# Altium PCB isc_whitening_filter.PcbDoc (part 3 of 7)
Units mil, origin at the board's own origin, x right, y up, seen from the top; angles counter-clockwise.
Board outline 8440 x 7000 mil, 6 copper layers (Top Layer, MidLayer1, InternalPlane1, Internal Plane 3, InternalPlane2, Bottom Layer); 550 components, 434 nets, 2189 pads, 806 vias.
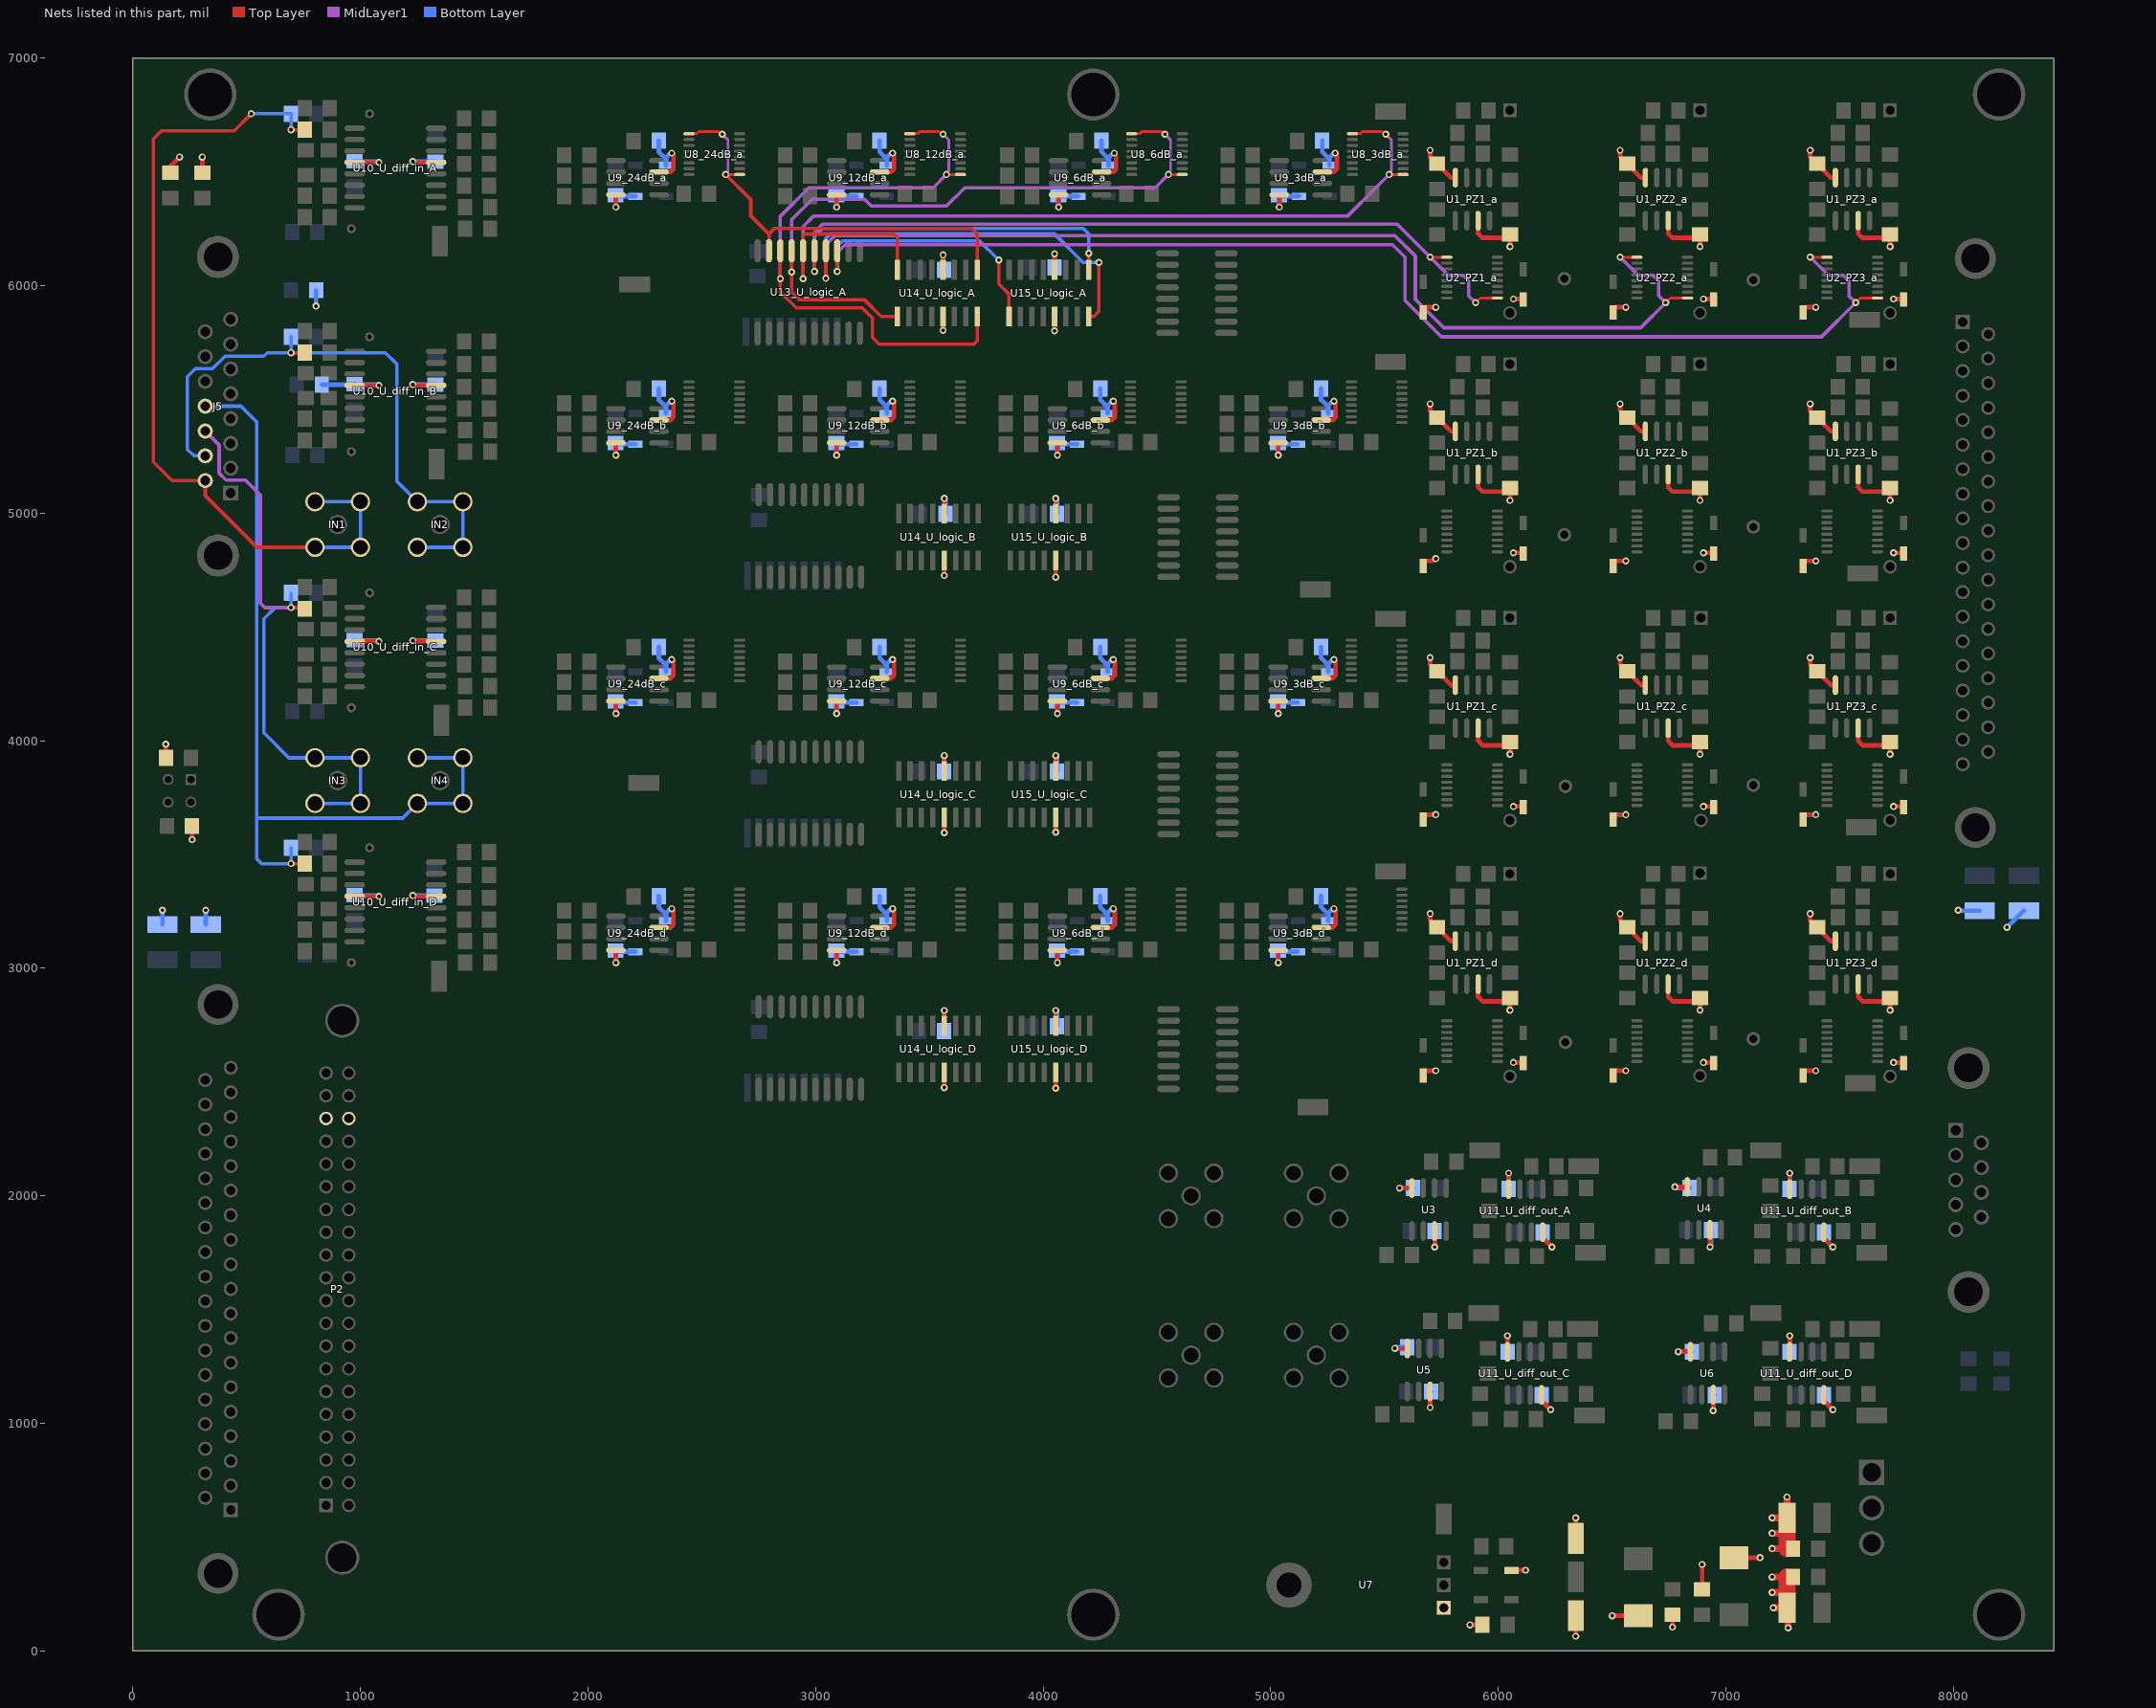
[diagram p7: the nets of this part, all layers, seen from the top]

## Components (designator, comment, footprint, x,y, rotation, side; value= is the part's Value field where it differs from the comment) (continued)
U8_6dB_b "ADG1436YRUZ-REEL7" ADI-RU-16_L 4495,5487.8 r180 top (schematic designator U8)
U8_6dB_c "ADG1436YRUZ-REEL7" ADI-RU-16_L 4495,4352.8 r180 top (schematic designator U8)
U8_6dB_d "ADG1436YRUZ-REEL7" ADI-RU-16_L 4495,3257.8 r180 top (schematic designator U8)
U8_12dB_a "ADG1436YRUZ-REEL7" ADI-RU-16_L 3525,6577.8 r180 top (schematic designator U8)
U8_12dB_b "ADG1436YRUZ-REEL7" ADI-RU-16_L 3525,5487.8 r180 top (schematic designator U8)
U8_12dB_c "ADG1436YRUZ-REEL7" ADI-RU-16_L 3525,4352.8 r180 top (schematic designator U8)
U8_12dB_d "ADG1436YRUZ-REEL7" ADI-RU-16_L 3525,3257.8 r180 top (schematic designator U8)
U8_24dB_a "ADG1436YRUZ-REEL7" ADI-RU-16_L 2555,6577.8 r180 top (schematic designator U8)
U8_24dB_b "ADG1436YRUZ-REEL7" ADI-RU-16_L 2555,5487.8 r180 top (schematic designator U8)
U8_24dB_c "ADG1436YRUZ-REEL7" ADI-RU-16_L 2555,4352.8 r180 top (schematic designator U8)
U8_24dB_d "ADG1436YRUZ-REEL7" ADI-RU-16_L 2555,3257.8 r180 top (schematic designator U8)
U9_3dB_a "OP27GS" SOIC127P600-8N 5132,6474 r0 top (schematic designator U9)
U9_3dB_b "OP27GS" SOIC127P600-8N 5127,5384 r0 top (schematic designator U9)
U9_3dB_c "OP27GS" SOIC127P600-8N 5127,4249 r0 top (schematic designator U9)
U9_3dB_d "OP27GS" SOIC127P600-8N 5127,3154 r0 top (schematic designator U9)
U9_6dB_a "OP27GS" SOIC127P600-8N 4162,6474 r0 top (schematic designator U9)
U9_6dB_b "OP27GS" SOIC127P600-8N 4157,5384 r0 top (schematic designator U9)
U9_6dB_c "OP27GS" SOIC127P600-8N 4157,4249 r0 top (schematic designator U9)
U9_6dB_d "OP27GS" SOIC127P600-8N 4157,3154 r0 top (schematic designator U9)
U9_12dB_a "OP27GS" SOIC127P600-8N 3187,6474 r0 top (schematic designator U9)
U9_12dB_b "OP27GS" SOIC127P600-8N 3187,5384 r0 top (schematic designator U9)
U9_12dB_c "OP27GS" SOIC127P600-8N 3187,4249 r0 top (schematic designator U9)
U9_12dB_d "OP27GS" SOIC127P600-8N 3187,3154 r0 top (schematic designator U9)
U9_24dB_a "OP27GS" SOIC127P600-8N 2217,6474 r0 top (schematic designator U9)
U9_24dB_b "OP27GS" SOIC127P600-8N 2217,5384 r0 top (schematic designator U9)
U9_24dB_c "OP27GS" SOIC127P600-8N 2217,4249 r0 top (schematic designator U9)
U9_24dB_d "OP27GS" SOIC127P600-8N 2217,3154 r0 top (schematic designator U9)
U10_U_diff_in_A "LT1125CSW" SOIC127P1030-16N 1153.66,6516.5 r0 top (schematic designator U10)
U10_U_diff_in_B "LT1125CSW" SOIC127P1030-16N 1153.66,5536.5 r0 top (schematic designator U10)
U10_U_diff_in_C "LT1125CSW" SOIC127P1030-16N 1153.66,4411.5 r0 top (schematic designator U10)
U10_U_diff_in_D "LT1125CSW" SOIC127P1030-16N 1153.66,3291.5 r0 top (schematic designator U10)
U11_U_diff_out_A "AD8672ARZ" SOIC127P600-8N 6120,1935 r270 top (schematic designator U11)
U11_U_diff_out_B "AD8672ARZ" SOIC127P600-8N 7355,1935 r270 top (schematic designator U11)
U11_U_diff_out_C "AD8672ARZ" SOIC127P600-8N 6115,1220 r270 top (schematic designator U11)
U11_U_diff_out_D "AD8672ARZ" SOIC127P600-8N 7355,1220 r270 top (schematic designator U11)
U13_U_logic_A "74ALS573" DW020_M 2970,5972 r90 top (schematic designator U13)
U13_U_logic_B "74ALS573" DW020_M 2975,4900 r90 top (schematic designator U13)
U13_U_logic_C "74ALS573" DW020_M 2975,3770 r90 top (schematic designator U13)
U13_U_logic_D "74ALS573" DW020_M 2975,2650 r90 top (schematic designator U13)
U14_U_logic_A "DG412" SOIC16 3535,5967 r180 top (schematic designator U14)
U14_U_logic_B "DG412" SOIC16 3540,4895 r180 top (schematic designator U14)
U14_U_logic_C "DG412" SOIC16 3540,3765 r180 top (schematic designator U14)
U14_U_logic_D "DG412" SOIC16 3540,2645 r180 top (schematic designator U14)
U15_U_logic_A "DG412" SOIC16 4025,5967 r180 top (schematic designator U15)
U15_U_logic_B "DG412" SOIC16 4030,4895 r180 top (schematic designator U15)
U15_U_logic_C "DG412" SOIC16 4030,3765 r180 top (schematic designator U15)
U15_U_logic_D "DG412" SOIC16 4030,2645 r180 top (schematic designator U15)

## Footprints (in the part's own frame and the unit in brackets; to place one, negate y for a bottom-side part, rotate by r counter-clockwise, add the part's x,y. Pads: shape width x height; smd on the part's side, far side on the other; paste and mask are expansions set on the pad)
1812 [mm]
  rect 1.9x3.4 smd: 1(-1.95,0) 2(1.95,0)
  silkscreen extent -0.7,-1.6 0.7,1.6, body extent -2.48,-1.9 2.47,1.91, height 3.42
3216[1206] [mm]
  rect 1.6x1.8 smd: 1(-1.4,0) 2(1.4,0)
  silkscreen extent -0.16,-0.8 0.15,0.79, body extent -1.67,-0.86 1.68,0.87, height 0.85
7343-31 [mil]
  rect 100x125 smd: 1(0,0) 2(-250,0)
  silkscreen extent -290,-85 40,85, body extent -271,-88 21,88
ADI-RU-16_L [mm] "SOP, 16-Leads, Body 5x4.4mm, Pitch 0.65mm, IPC High Density"
  oval 1.25x0.35 smd: 1(-2.825,2.275) 2(-2.825,1.625) 3(-2.825,0.975) 4(-2.825,0.325) 5(-2.825,-0.325) 6(-2.825,-0.975) 7(-2.825,-1.625) 8(-2.825,-2.275) 9(2.825,-2.275) 10(2.825,-1.625) 11(2.825,-0.975) 12(2.825,-0.325) 13(2.825,0.325) 14(2.825,0.975) 15(2.825,1.625) 16(2.825,2.275)
  silkscreen extent -2.95,-2.55 1.8,3.12, body extent -2.25,-2.55 2.25,2.55, height 1.2
DB37/F/RA/125MT [mil]
  rect 62x62 hole 40.5: 1(0,0)
  round 62 hole 40.5: 2(107,0) 3(215,0) 4(324,0) 5(431,0) 6(539,0) 7(647,0) 8(755,0) 9(863,0) 10(971,0) 11(1079,0) 12(1187,0) 13(1295,0) 14(1403,0) 15(1511,0) 16(1619,0) 17(1727,0) 18(1835,0) 19(1943,0) 20(53,112) 21(161,112) 22(269,112) 23(377,112) 24(485,112) 25(593,112) 26(701,112) 27(809,112) 28(917,112) 29(1025,112) 30(1133,112) 31(1241,112) 32(1349,112) 33(1457,112) 34(1565,112) 35(1673,112) 36(1781,112) 37(1889,112)
  round 180 hole 125.9: 38(-279,56) 39(2221,56)
  silkscreen extent -394,-98 2336,666, body extent -402,-72 2336,673, height 497
DSUB1.385-2H9 [mm]
  rect 1.69x1.69 hole 1.097: 1(-5.54,-10.92)
  round 1.69 hole 1.097: 2(-2.77,-10.92) 3(0,-10.92) 4(2.77,-10.92) 5(5.54,-10.92) 6(-4.155,-8.08) 7(-1.385,-8.08) 8(1.385,-8.08) 9(4.155,-8.08)
  round 4.699 hole 3.198: 10(-12.495,-9.5) 11(12.495,-9.5)
  silkscreen extent -15.4,-12.4 15.4,6, body extent -15.49,-12.67 15.49,6.22, height 12.62
DSUB1.385-2H15 [mm]
  rect 1.69x1.69 hole 1.097: 1(-9.695,-10.92)
  round 1.69 hole 1.097: 2(-6.925,-10.92) 3(-4.155,-10.92) 4(-1.385,-10.92) 5(1.385,-10.92) 6(4.155,-10.92) 7(6.925,-10.92) 8(9.695,-10.92) 9(-8.31,-8.08) 10(-5.54,-8.08) 11(-2.77,-8.08) 12(0,-8.08) 13(2.77,-8.08) 14(5.54,-8.08) 15(8.31,-8.08)
  round 4.699 hole 3.198: 16(-16.66,-9.5) 17(16.66,-9.5)
  silkscreen extent -20,-12.5 20,6, body extent -19.68,-12.67 19.69,6.22, height 12.62
DW020_M [mm]
  oval 2.6x0.7 smd: 1(-4.6,5.715) 2(-4.6,4.445) 3(-4.6,3.175) 4(-4.6,1.905) 5(-4.6,0.635) 6(-4.6,-0.635) 7(-4.6,-1.905) 8(-4.6,-3.175) 9(-4.6,-4.445) 10(-4.6,-5.715) 11(4.6,-5.715) 12(4.6,-4.445) 13(4.6,-3.175) 14(4.6,-1.905) 15(4.6,-0.635) 16(4.6,0.635) 17(4.6,1.905) 18(4.6,3.175) 19(4.6,4.445) 20(4.6,5.715)
  silkscreen extent -4.72,-6.5 2.9,6.74, body extent -5.24,-6.42 5.24,6.43, height 2.65
ECQ-E1106KF_Side [mil]
  rect 60x60 hole 40.5: 1(0,0)
  round 60 hole 40.5: 2(890,0)
  silkscreen extent -50,-50 950,340, body extent -62,-688 962,926
Molex_156_RA_3 [mil]
  rect 110x110 hole 80: 1(0,0)
  round 110 hole 80: 2(0,-156) 3(0,-312)
  silkscreen extent 213,-382 792,70, body extent -24,-386 792,76, height 394
"my LUMEX Dual LED" [mil]
  rect 48x48 hole 32: 1(0,0)
  round 48 hole 32: 2(0,-100) 3(-100,0) 4(-100,-100)
  silkscreen extent -320,-140 45,40, body extent -379,-135 45,35, height 380
MY_40-pin_Header_RA [mil]
  rect 60x60 hole 40.5 mask+0: 1(230,-71)
  round 60 hole 40.5 mask+0: 2(230,29) 3(330,-71) 4(330,29) 5(430,-71) 6(430,29) 7(530,-71) 8(530,29) 9(630,-71) 10(630,29) 11(730,-71) 12(730,29) 13(830,-71) 14(830,29) 15(930,-71) 16(930,29) 17(1030,-71) 18(1030,29) 19(1130,-71) 20(1130,29) 21(1230,-71) 22(1230,29) 23(1330,-71) 24(1330,29) 25(1430,-71) 26(1430,29) 27(1530,-71) 28(1530,29) 29(1630,-71) 30(1630,29) 31(1730,-71) 32(1730,29) 33(1830,-71) 34(1830,29) 35(1930,-71) 36(1930,29) 37(2030,-71) 38(2030,29) 39(2130,-71) 40(2130,29)
  round 150 hole 125.9 mask+0: 41(2360,0) 42(0,0)
  silkscreen extent -220,-120 2580,440, body extent -200,-148 2560,978, height 344
MY_TO220 [mil]
  rect 62x62 hole 40.5: 1(-100,0) 2(0,0) 3(100,0)
  round 200 hole 110: 4(0,680)
  silkscreen extent -200,60 200,800, body extent -200,-85 200,795, height 180
SMA [mil] "SMA straight PCB"
  round 85 hole 65: 1(0,0) 2(-100,100) 2(-100,-100) 2(100,100) 2(100,-100)
  silkscreen extent -160,-160 160,160, body extent -126,-126 126,126, height 370
sod123 [mm]
  rect 1.6x0.8 smd: 1(-1.7,0) 2(1.7,0)
  silkscreen extent -1.45,-0.85 1.45,0.85, body extent -1.95,-0.9 1.95,0.9, height 1.18
SOIC16 [mm]
  rect 0.6x2.2 smd: 1(-4.445,-2.6) 2(-3.175,-2.6) 3(-1.905,-2.6) 4(-0.635,-2.6) 5(0.635,-2.6) 6(1.905,-2.6) 7(3.175,-2.6) 8(4.445,-2.6) 9(4.445,2.6) 10(3.175,2.6) 11(1.905,2.6) 12(0.635,2.6) 13(-0.635,2.6) 14(-1.905,2.6) 15(-3.175,2.6) 16(-4.445,2.6)
  silkscreen extent -5.42,-2.72 5,1.1, body extent -4.98,-3.06 4.97,3.06, height 1.75
SOIC127P600-8N [mm]
  oval 2.2x0.6 smd: 1(-2.4,1.905) 2(-2.4,0.635) 3(-2.4,-0.635) 4(-2.4,-1.905) 5(2.4,-1.905) 6(2.4,-0.635) 7(2.4,0.635) 8(2.4,1.905)
  silkscreen extent -2.52,-2.5 0.9,2.88, body extent -3.06,-2.47 3.06,2.48, height 1.75
SOIC127P1030-16N [mm]
  oval 2.3x0.6 smd: 1(-4.55,4.445) 2(-4.55,3.175) 3(-4.55,1.905) 4(-4.55,0.635) 5(-4.55,-0.635) 6(-4.55,-1.905) 7(-4.55,-3.175) 8(-4.55,-4.445) 9(4.55,-4.445) 10(4.55,-3.175) 11(4.55,-1.905) 12(4.55,-0.635) 13(4.55,0.635) 14(4.55,1.905) 15(4.55,3.175) 16(4.55,4.445)
  silkscreen extent -4.67,-5.25 3,5.42, body extent -5.24,-5.18 5.24,5.18, height 2.65
SOP127P760X300-16M [mm]
  oval 2.55x0.7 smd: 1(-3.275,4.445) 2(-3.275,3.175) 3(-3.275,1.905) 4(-3.275,0.635) 5(-3.275,-0.635) 6(-3.275,-1.905) 7(-3.275,-3.175) 8(-3.275,-4.445) 9(3.275,-4.445) 10(3.275,-3.175) 11(3.275,-1.905) 12(3.275,-0.635) 13(3.275,0.635) 14(3.275,1.905) 15(3.275,3.175) 16(3.275,4.445)
  silkscreen extent -3.4,-5.65 1.6,5.65, body extent -3.06,-4.97 3.06,4.98, height 1.75
SRT9 [mil]
  rect 125x30 smd: 1(0,0) 2(0,-50) 3(0,-100) 4(0,-150) 5(0,-200) 6(0,-250) 7(0,-300) 8(0,-350) 9(0,-400)
  silkscreen extent -53,-450 55,52, body extent -40,-450 40,50, height 100
TP_SMT_MICRO [mil]
  rect 135x70 smd: 1(0,0)
  body extent -53,-20 52,20, height 60

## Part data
C1_PZ1_a C1_PZ1_b C1_PZ1_c C1_PZ1_d C1_PZ2_a C1_PZ2_b C1_PZ2_c C1_PZ2_d C1_PZ3_a C1_PZ3_b C1_PZ3_c C1_PZ3_d C3_PZ1_a C3_PZ1_b C3_PZ1_c C3_PZ1_d C3_PZ2_a C3_PZ2_b C3_PZ2_c C3_PZ2_d C3_PZ3_a C3_PZ3_b C3_PZ3_c C3_PZ3_d C6 C8 C9 C11 C12 C14 C15 C17 C19 C22 C24_3dB_a C24_3dB_b C24_3dB_c C24_3dB_d C24_6dB_a C24_6dB_b C24_6dB_c C24_6dB_d C24_12dB_a C24_12dB_b C24_12dB_c C24_12dB_d C24_24dB_a C24_24dB_b C24_24dB_c C24_24dB_d C26_3dB_a C26_3dB_b C26_3dB_c C26_3dB_d C26_6dB_a C26_6dB_b C26_6dB_c C26_6dB_d C26_12dB_a C26_12dB_b C26_12dB_c C26_12dB_d C26_24dB_a C26_24dB_b C26_24dB_c C26_24dB_d C30_U_diff_out_A C30_U_diff_out_B C30_U_diff_out_C C30_U_diff_out_D C31_U_diff_out_A C31_U_diff_out_B C31_U_diff_out_C C31_U_diff_out_D C32_U_logic_A C32_U_logic_B C32_U_logic_C C32_U_logic_D C33_U_logic_A C33_U_logic_B C33_U_logic_C C33_U_logic_D C36_U_logic_A C36_U_logic_B C36_U_logic_C C36_U_logic_D: library part Cap, "Capacitor", Supplier Part Number 1=399-C1206C104K5RACTUCT-ND
C2_PZ1_a C2_PZ1_b C2_PZ1_c C2_PZ1_d C2_PZ2_a C2_PZ2_b C2_PZ2_c C2_PZ2_d C2_PZ3_a C2_PZ3_b C2_PZ3_c C2_PZ3_d C7 C10 C13 C16 C25_3dB_a C25_3dB_b C25_3dB_c C25_3dB_d C25_6dB_a C25_6dB_b C25_6dB_c C25_6dB_d C25_12dB_a C25_12dB_b C25_12dB_c C25_12dB_d C25_24dB_a C25_24dB_b C25_24dB_c C25_24dB_d: library part Cap, "Capacitor", Supplier Part Number 1=399-C1206C680K1HACAUTOCT-ND
C4_PZ1_a C4_PZ1_b C4_PZ1_c C4_PZ1_d C4_PZ2_a C4_PZ2_b C4_PZ2_c C4_PZ2_d C4_PZ3_a C4_PZ3_b C4_PZ3_c C4_PZ3_d: library part Cap, "Capacitor", Supplier Part Number 1=399-C1206C101K5HACTUCT-ND
C5_PZ1_a C5_PZ1_b C5_PZ1_c C5_PZ1_d C5_PZ2_a C5_PZ2_b C5_PZ2_c C5_PZ2_d C5_PZ3_a C5_PZ3_b C5_PZ3_c C5_PZ3_d: library part MYCAP, "Capacitor", Supplier Part Number 1=P14629-ND
C18 C23: library part "CAPACITOR POL", "Polarized Cap", Supplier Part Number 1=478-1722-1-ND
C20 C21 C28_U_diff_in_A C28_U_diff_in_B C28_U_diff_in_C C28_U_diff_in_D C29_U_diff_in_A C29_U_diff_in_B C29_U_diff_in_C C29_U_diff_in_D C34 C35: library part MYCAP, "Capacitor", Supplier Part Number 1=1276-1068-1-ND
C27_3dB_a C27_3dB_b C27_3dB_c C27_3dB_d C27_6dB_a C27_6dB_b C27_6dB_c C27_6dB_d C27_12dB_a C27_12dB_b C27_12dB_c C27_12dB_d C27_24dB_a C27_24dB_b C27_24dB_c C27_24dB_d: library part Cap, "Capacitor"
C37_U_diff_in_A C37_U_diff_in_B C37_U_diff_in_C C37_U_diff_in_D C38_U_diff_in_A C38_U_diff_in_B C38_U_diff_in_C C38_U_diff_in_D C39_U_diff_in_A C39_U_diff_in_B C39_U_diff_in_C C39_U_diff_in_D: library part MYCAP, "Capacitor", Supplier Part Number 1=13-CC1206FRNPO9BN562CT-ND
D1_PZ1_a D1_PZ1_b D1_PZ1_c D1_PZ1_d D1_PZ2_a D1_PZ2_b D1_PZ2_c D1_PZ2_d D1_PZ3_a D1_PZ3_b D1_PZ3_c D1_PZ3_d D2_PZ1_a D2_PZ1_b D2_PZ1_c D2_PZ1_d D2_PZ2_a D2_PZ2_b D2_PZ2_c D2_PZ2_d D2_PZ3_a D2_PZ3_b D2_PZ3_c D2_PZ3_d D3 D5 D6_3dB_a D6_3dB_b D6_3dB_c D6_3dB_d D6_6dB_a D6_6dB_b D6_6dB_c D6_6dB_d D6_12dB_a D6_12dB_b D6_12dB_c D6_12dB_d D6_24dB_a D6_24dB_b D6_24dB_c D6_24dB_d D7_3dB_a D7_3dB_b D7_3dB_c D7_3dB_d D7_6dB_a D7_6dB_b D7_6dB_c D7_6dB_d D7_12dB_a D7_12dB_b D7_12dB_c D7_12dB_d D7_24dB_a D7_24dB_b D7_24dB_c D7_24dB_d: library part Diode, "Diode 1 Amp", Supplier Part Number 1=RB160MM-60CT-ND
D4: library part "Dual Stacked LED", "Dual Green LED", Supplier Part Number 1=67-1321-ND
IN1 IN2 IN3 IN4 OUT1 OUT2 OUT3 OUT4: "SMA, PCB Mount, Right Angle", Supplier Part Number 1=900-0732517040-ND
J5: "15 Position, Right Angle, Receptacle Assembly", Supplier Part Number 1=D15S33E6GX00LF-ND
J6: "9 Position, Right Angle,Receptacle Assembly", Supplier Part Number 1=609-6160-ND
L1 L2: library part INDUCTOR, "INDUCTOR"
L5 L6 L7 L8: library part INDUCTOR, "INDUCTOR", Supplier Part Number 1=CC453232-100KLCT-ND
P1 P3: "Standard D-Subminiature Connector 37 pin", Supplier Part Number 1=D37S33E6GX00LF-ND
P2: "Header, 20-Pin, Dual row, Right Angle", Supplier Part Number 1=609-86130402113345E1LF-ND
P4: "Header, 3-Pin, Right Angle", Supplier Part Number 1=WM5236-ND
R1_PZ1_a R1_PZ1_b R1_PZ1_c R1_PZ1_d R1_PZ2_a R1_PZ2_b R1_PZ2_c R1_PZ2_d R1_PZ3_a R1_PZ3_b R1_PZ3_c R1_PZ3_d R11_3dB_a R11_3dB_b R11_3dB_c R11_3dB_d R11_6dB_a R11_6dB_b R11_6dB_c R11_6dB_d R11_12dB_a R11_12dB_b R11_12dB_c R11_12dB_d R11_24dB_a R11_24dB_b R11_24dB_c R11_24dB_d R30_PZ1_a R30_PZ1_b R30_PZ1_c R30_PZ1_d R30_PZ2_a R30_PZ2_b R30_PZ2_c R30_PZ2_d R30_PZ3_a R30_PZ3_b R30_PZ3_c R30_PZ3_d: library part Res1, "Resistor", Supplier Part Number 1=10-ERA-8AEB153VCT-ND
R2_PZ1_a R2_PZ1_b R2_PZ1_c R2_PZ1_d R2_PZ2_a R2_PZ2_b R2_PZ2_c R2_PZ2_d R2_PZ3_a R2_PZ3_b R2_PZ3_c R2_PZ3_d: library part Res1, "Resistor", Supplier Part Number 1=P18589CT-ND
R3 R4 R5 R6 R17_U_diff_in_A R17_U_diff_in_B R17_U_diff_in_C R17_U_diff_in_D R19_U_diff_in_A R19_U_diff_in_B R19_U_diff_in_C R19_U_diff_in_D R23_U_diff_out_A R23_U_diff_out_B R23_U_diff_out_C R23_U_diff_out_D R26_U_diff_out_A R26_U_diff_out_B R26_U_diff_out_C R26_U_diff_out_D R35 R36 R38 R39: library part Res1, "Resistor", Supplier Part Number 1=HCJ1206ZT0R00CT-ND
R7 R8 R9 R10 R32_U_diff_in_A R32_U_diff_in_B R32_U_diff_in_C R32_U_diff_in_D R33_U_diff_in_A R33_U_diff_in_B R33_U_diff_in_C R33_U_diff_in_D: library part Res1, "Resistor", Supplier Part Number 1=P1.0KBCCT-ND
R12_3dB_a R12_3dB_b R12_3dB_c R12_3dB_d R12_6dB_a R12_6dB_b R12_6dB_c R12_6dB_d R12_12dB_a R12_12dB_b R12_12dB_c R12_12dB_d R12_24dB_a R12_24dB_b R12_24dB_c R12_24dB_d R13_3dB_a R13_3dB_b R13_3dB_c R13_3dB_d R13_6dB_a R13_6dB_b R13_6dB_c R13_6dB_d R13_12dB_a R13_12dB_b R13_12dB_c R13_12dB_d R13_24dB_a R13_24dB_b R13_24dB_c R13_24dB_d R18_U_diff_in_A R18_U_diff_in_B R18_U_diff_in_C R18_U_diff_in_D: library part Res1, "Resistor"
R14_U_diff_in_A R14_U_diff_in_B R14_U_diff_in_C R14_U_diff_in_D R22_U_diff_in_A R22_U_diff_in_B R22_U_diff_in_C R22_U_diff_in_D: library part Res1, "Resistor", Supplier Part Number 1=P1.0MBCCT-ND
R15_U_diff_in_A R15_U_diff_in_B R15_U_diff_in_C R15_U_diff_in_D R21_U_diff_in_A R21_U_diff_in_B R21_U_diff_in_C R21_U_diff_in_D: library part Res1, "Resistor", Supplier Part Number 1=10-ERA-8AEB302VCT-ND
R16_U_diff_in_A R16_U_diff_in_B R16_U_diff_in_C R16_U_diff_in_D R20_U_diff_in_A R20_U_diff_in_B R20_U_diff_in_C R20_U_diff_in_D: library part Res1, "Resistor", Supplier Part Number 1=P1.5KBCCT-ND
R24_U_diff_out_A R24_U_diff_out_B R24_U_diff_out_C R24_U_diff_out_D R25_U_diff_out_A R25_U_diff_out_B R25_U_diff_out_C R25_U_diff_out_D R27_U_diff_out_A R27_U_diff_out_B R27_U_diff_out_C R27_U_diff_out_D R28_U_diff_out_A R28_U_diff_out_B R28_U_diff_out_C R28_U_diff_out_D: library part Res1, "Resistor", Supplier Part Number 1=P4.99KBCCT-ND
R29_U_logic_A R29_U_logic_B R29_U_logic_C R29_U_logic_D: library part RES_BUS_8, "8 Bus Resistor", Supplier Part Number 1=60-752091103GPTR7CT-ND
R31_U_logic_A R31_U_logic_B R31_U_logic_C R31_U_logic_D: library part "Res Pack3", "Isolated Resistor Network", Supplier Part Number 1=4816P-1-561LFCT-ND
R34 R37: library part Res1, "Resistor", Supplier Part Number 1=P49.9BCCT-ND
TP1 TP2 TP3 TP4 TP5 TP6 TP7_U_diff_out_A TP7_U_diff_out_B TP7_U_diff_out_C TP7_U_diff_out_D TP8_U_diff_out_A TP8_U_diff_out_B TP8_U_diff_out_C TP8_U_diff_out_D TP9 TP9_U_diff_out_A TP9_U_diff_out_B TP9_U_diff_out_C TP9_U_diff_out_D TP10 TP11 TP12 TP13 TP14 TP15 TP16 TP17 TP18 TP19 TP20 TP21 TP22: library part TESTPT, "PCB Testpoint", Supplier Part Number 1=36-5016CT-ND
U1_PZ1_a U1_PZ1_b U1_PZ1_c U1_PZ1_d U1_PZ2_a U1_PZ2_b U1_PZ2_c U1_PZ2_d U1_PZ3_a U1_PZ3_b U1_PZ3_c U1_PZ3_d U3 U4 U5 U6 U9_3dB_a U9_3dB_b U9_3dB_c U9_3dB_d U9_6dB_a U9_6dB_b U9_6dB_c U9_6dB_d U9_12dB_a U9_12dB_b U9_12dB_c U9_12dB_d U9_24dB_a U9_24dB_b U9_24dB_c U9_24dB_d: library part OP184ES, "Video Operational Amplifier", Supplier Part Number 1=OP27GSZ-REEL7CT-ND
U2_PZ1_a U2_PZ1_b U2_PZ1_c U2_PZ1_d U2_PZ2_a U2_PZ2_b U2_PZ2_c U2_PZ2_d U2_PZ3_a U2_PZ3_b U2_PZ3_c U2_PZ3_d U8_3dB_a U8_3dB_b U8_3dB_c U8_3dB_d U8_6dB_a U8_6dB_b U8_6dB_c U8_6dB_d U8_12dB_a U8_12dB_b U8_12dB_c U8_12dB_d U8_24dB_a U8_24dB_b U8_24dB_c U8_24dB_d: library part CMP-0793-00126-1, "+/-15 V / 12 V / +/-5 V, iCMOS, Dual SPDT Switch, 16-pin SOP (RU-16), Reel"
U7: library part MC7805CD2T, "Three-Terminal Positive Voltage Regulator", Supplier Part Number 1=497-2957-5-ND
U10_U_diff_in_A U10_U_diff_in_B U10_U_diff_in_C U10_U_diff_in_D: library part LT1125CS, "Quad Low Noise, High-Speed Precision Operational Amplifier", Supplier Part Number 1=505-LT1125CSW#PBF-ND
U11_U_diff_out_A U11_U_diff_out_B U11_U_diff_out_C U11_U_diff_out_D: library part AD826AR, "High-Speed, Low-Power Dual Operational Amplifier", Supplier Part Number 1=505-AD8672ARZ-ND
U13_U_logic_A U13_U_logic_B U13_U_logic_C U13_U_logic_D: library part SN74ALS573CDW, "Octal D-Type Transparent Latches with 3-State Outputs", Supplier Part Number 1=296-1129-1-ND
U14_U_logic_A U14_U_logic_B U14_U_logic_C U14_U_logic_D U15_U_logic_A U15_U_logic_B U15_U_logic_C U15_U_logic_D: "Quad Analog SPST NO Switch", Supplier Part Number 1=DG412DY-T1-E3CT-ND

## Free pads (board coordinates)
  round 40 hole 20 mask+0: 0(1040,3530) 0(1040,4650) 0(1040,5775) 0(1040,6755) 1(960,3025) 1(960,4145) 1(960,5270) 1(960,6250)
  round 60 hole 36 mask+0: 0(6290,6030) 1(7120,6025) 2(6290,4905) 3(6295,3800) 4(6295,2675) 5(7120,4940) 6(7120,3805) 7(7120,2690)
  round 230 hole 193: 5(4220,6840) 6(340,6840) 6(640,160) 6(4220,160) 7(8200,160) 8(8200,6840)

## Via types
v1: diameter 31, hole 16, Top Layer to Bottom Layer, 805 vias
v2: diameter 45, hole 20, Top Layer to Bottom Layer, 1 vias

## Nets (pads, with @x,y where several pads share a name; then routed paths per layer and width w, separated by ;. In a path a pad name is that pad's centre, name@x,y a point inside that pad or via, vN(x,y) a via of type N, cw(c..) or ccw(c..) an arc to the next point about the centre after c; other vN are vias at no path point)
+15: C3_PZ1_a.2 C3_PZ1_b.2 C3_PZ1_c.2 C3_PZ1_d.2 C3_PZ2_a.2 C3_PZ2_b.2 C3_PZ2_c.2 C3_PZ2_d.2 C3_PZ3_a.2 C3_PZ3_b.2 C3_PZ3_c.2 C3_PZ3_d.2 C8.2 C11.2 C14.2 C17.2 C18.1 C19.1 C20.2 C26_3dB_a.2 C26_3dB_b.2 C26_3dB_c.2 C26_3dB_d.2 C26_6dB_a.2 C26_6dB_b.2 C26_6dB_c.2 C26_6dB_d.2 C26_12dB_a.2 C26_12dB_b.2 C26_12dB_c.2 C26_12dB_d.2 C26_24dB_a.2 C26_24dB_b.2 C26_24dB_c.2 C26_24dB_d.2 C28_U_diff_in_A.1 C28_U_diff_in_B.1 C28_U_diff_in_C.1 C28_U_diff_in_D.1 C30_U_diff_out_A.1 C30_U_diff_out_B.1 C30_U_diff_out_C.1 C30_U_diff_out_D.1 D2_PZ1_a.1 D2_PZ1_b.1 D2_PZ1_c.1 D2_PZ1_d.1 D2_PZ2_a.1 D2_PZ2_b.1 D2_PZ2_c.1 D2_PZ2_d.1 D2_PZ3_a.1 D2_PZ3_b.1 D2_PZ3_c.1 D2_PZ3_d.1 D3.2 D7_3dB_a.1 D7_3dB_b.1 D7_3dB_c.1 D7_3dB_d.1 D7_6dB_a.1 D7_6dB_b.1 D7_6dB_c.1 D7_6dB_d.1 D7_12dB_a.1 D7_12dB_b.1 D7_12dB_c.1 D7_12dB_d.1 D7_24dB_a.1 D7_24dB_b.1 D7_24dB_c.1 D7_24dB_d.1 L1.2 L5.2 L6.2 L7.2 L8.2 P2.35 P2.36 R7.2 R10.2 R35.2 R38.2 TP3.1 U1_PZ1_a.7 U1_PZ1_b.7 U1_PZ1_c.7 U1_PZ1_d.7 U1_PZ2_a.7 U1_PZ2_b.7 U1_PZ2_c.7 U1_PZ2_d.7 U1_PZ3_a.7 U1_PZ3_b.7 U1_PZ3_c.7 U1_PZ3_d.7 U3.7 U4.7 U5.7 U6.7 U7.1 U9_3dB_a.7 U9_3dB_b.7 U9_3dB_c.7 U9_3dB_d.7 U9_6dB_a.7 U9_6dB_b.7 U9_6dB_c.7 U9_6dB_d.7 U9_12dB_a.7 U9_12dB_b.7 U9_12dB_c.7 U9_12dB_d.7 U9_24dB_a.7 U9_24dB_b.7 U9_24dB_c.7 U9_24dB_d.7 U10_U_diff_in_A.4 U10_U_diff_in_B.4 U10_U_diff_in_C.4 U10_U_diff_in_D.4 U11_U_diff_out_A.8 U11_U_diff_out_B.8 U11_U_diff_out_C.8 U11_U_diff_out_D.8 U14_U_logic_A.13 U14_U_logic_B.13 U14_U_logic_C.13 U14_U_logic_D.13 U15_U_logic_A.13 U15_U_logic_B.13 U15_U_logic_C.13 U15_U_logic_D.13 | length 12763.1
  Top Layer w20: R10.2@144.88,3925 v1(144.88,3984.88) v1@145,3985 ; R7.2@305,6495.12 v1(305,6565) ; U10_U_diff_in_D.4@974.53,3316.5 v1(1081.5,3316.5) ; U10_U_diff_in_C.4@974.53,4436.5 v1(1081.5,4436.5) ; U10_U_diff_in_B.4@974.53,5561.5 v1(1081.5,5561.5) ; U10_U_diff_in_A.4@974.53,6541.5 v1(1081.5,6541.5) ; U9_24dB_d.7@2311.49,3179 2311.55,3179.06 2362.06,3179.06 2375,3192 2375,3252.02 2367.87,3259.16 v1(2367.87,3262.13) ; U9_24dB_c.7@2311.49,4274 2311.55,4274.06 2362.06,4274.06 2375,4287 2375,4347.02 2367.87,4354.16 v1(2367.87,4357.13) ; U9_24dB_b.7@2311.49,5409 2311.55,5409.06 2362.06,5409.06 2375,5422 2375,5482.02 2367.87,5489.16 v1(2367.87,5492.13) ; U9_24dB_a.7@2311.49,6499 2311.55,6499.06 2362.06,6499.06 2375,6512 2375,6572.02 2367.87,6579.16 v1(2367.87,6582.13) ; U9_12dB_d.7@3281.49,3179 3281.55,3179.06 3332.06,3179.06 3345,3192 3345,3252.02 3337.87,3259.16 v1(3337.87,3262.13) ; U9_12dB_c.7@3281.49,4274 3281.55,4274.06 3332.06,4274.06 3345,4287 3345,4347.02 3337.87,4354.16 v1(3337.87,4357.13) ; U9_12dB_b.7@3281.49,5409 3281.55,5409.06 3332.06,5409.06 3345,5422 3345,5482.02 3337.87,5489.16 v1(3337.87,5492.13) ; U9_12dB_a.7@3281.49,6499 3281.55,6499.06 3332.06,6499.06 3345,6512 3345,6572.02 3337.87,6579.16 v1(3337.87,6582.13) ; v1(3560,5803) U14_U_logic_A.13@3560,5864.64 ; v1(3565,2476) U14_U_logic_D.13@3565,2542.64 ; v1(3565,3596) U14_U_logic_C.13@3565,3662.64 ; v1(3565,4726) U14_U_logic_B.13@3565,4792.64 ; v1(4050,5801) U15_U_logic_A.13@4050,5864.64 ; v1(4055,2473) U15_U_logic_D.13@4055,2542.64 ; v1(4055,3598) U15_U_logic_C.13@4055,3662.64 ; v1(4055,4719) U15_U_logic_B.13@4055,4792.64 ; U9_6dB_d.7@4251.49,3179 4251.55,3179.06 4302.06,3179.06 4315,3192 4315,3252.02 4307.87,3259.16 v1(4307.87,3262.13) ; U9_6dB_c.7@4251.49,4274 4251.55,4274.06 4302.06,4274.06 4315,4287 4315,4347.02 4307.87,4354.16 v1(4307.87,4357.13) ; U9_6dB_b.7@4251.49,5409 4251.55,5409.06 4302.06,5409.06 4315,5422 4315,5482.02 4307.87,5489.16 v1(4307.87,5492.13) ; U9_6dB_a.7@4256.49,6499 4256.55,6499.06 4307.06,6499.06 4320,6512 4320,6572.02 4312.87,6579.16 v1(4312.87,6582.13) ; U9_3dB_d.7@5221.49,3179 5221.55,3179.06 5272.06,3179.06 5285,3192 5285,3252.02 5277.87,3259.16 v1(5277.87,3262.13) ; U9_3dB_c.7@5221.49,4274 5221.55,4274.06 5272.06,4274.06 5285,4287 5285,4347.02 5277.87,4354.16 v1(5277.87,4357.13) ; U9_3dB_b.7@5221.49,5409 5221.55,5409.06 5272.06,5409.06 5285,5422 5285,5482.02 5277.87,5489.16 v1(5277.87,5492.13) ; U9_3dB_a.7@5226.49,6499 5226.55,6499.06 5277.06,6499.06 5290,6512 5290,6572.02 5282.87,6579.16 v1(5282.87,6582.13) ; v1(5700,1070) U5.7@5700,1140.51 ; v1(5720,1775) U3.7@5720,1845.51 ; v1(5875,115) C20.2@5929.88,115 ; U1_PZ1_d.7@5911,2930.51 5911,2874 5930,2855 6036.12,2855 C3_PZ1_d.2@6051,2869.88 v1(6051,2816) v1@6050,2815 ; U1_PZ1_c.7@5911,4055.51 5911,3999 5930,3980 6036.12,3980 C3_PZ1_c.2@6051,3994.88 v1(6051,3941) v1@6050,3940 ; U1_PZ1_b.7@5911,5170.51 5911,5114 5930,5095 6036.12,5095 C3_PZ1_b.2@6051,5109.88 v1(6051,5056) v1@6050,5055 ; U1_PZ1_a.7@5911,6285.51 5911,6229 5930,6210 6036.12,6210 C3_PZ1_a.2@6051,6224.88 v1(6051,6171) v1@6050,6170 ; D3.2@6056.93,355 v1(6120,355) ; v1(6066,2586) 6107.07,2586 D2_PZ1_d.1@6110,2583.07 ; v1(6066,3711) 6107.07,3711 D2_PZ1_c.1@6110,3708.07 ; v1(6066,4826) 6107.07,4826 D2_PZ1_b.1@6110,4823.07 ; v1(6066,5941) 6107.07,5941 D2_PZ1_a.1@6110,5938.07 ; U11_U_diff_out_C.8@6190,1125.51 6190,1100 v1(6230,1060) v1@6235,1060 ; U11_U_diff_out_A.8@6195,1840.51 6195,1815 v1(6235,1775) v1@6240,1775 ; TP3.1@6340,495 v1(6340,585) ; U1_PZ2_d.7@6746,2930.51 6746,2874 6765,2855 6871.12,2855 C3_PZ2_d.2@6886,2869.88 v1(6886,2816) v1@6885,2815 ; U1_PZ2_c.7@6746,4055.51 6746,3999 6765,3980 6871.12,3980 C3_PZ2_c.2@6886,3994.88 v1(6886,3941) v1@6885,3940 ; U1_PZ2_b.7@6746,5170.51 6746,5114 6765,5095 6871.12,5095 C3_PZ2_b.2@6886,5109.88 v1(6886,5056) v1@6885,5055 ; U1_PZ2_a.7@6746,6285.51 6746,6229 6765,6210 6871.12,6210 C3_PZ2_a.2@6886,6224.88 v1(6886,6171) v1@6885,6170 ; C19.1@6895,270.12 v1(6895,380) ; v1(6901,2586) 6942.07,2586 D2_PZ2_d.1@6945,2583.07 ; v1(6901,3711) 6942.07,3711 D2_PZ2_c.1@6945,3708.07 ; v1(6901,4826) 6942.07,4826 D2_PZ2_b.1@6945,4823.07 ; v1(6901,5941) 6942.07,5941 D2_PZ2_a.1@6945,5938.07 ; v1@6925,1770 v1(6930,1775) U4.7@6930,1850.51 ; U6.7@6944,1126.51 v1(6944,1056) v1@6945,1055 ; C18.1@7035,410 v1(7150,410) ; U11_U_diff_out_D.8@7430,1125.51 7430,1100 v1(7470,1060) v1@7475,1060 ; U11_U_diff_out_B.8@7430,1840.51 7430,1815 v1(7470,1775) v1@7475,1775 ; U1_PZ3_d.7@7581,2930.51 7581,2874 7600,2855 7706.12,2855 C3_PZ3_d.2@7721,2869.88 v1(7721,2816) v1@7720,2815 ; U1_PZ3_c.7@7581,4055.51 7581,3999 7600,3980 7706.12,3980 C3_PZ3_c.2@7721,3994.88 v1(7721,3941) v1@7720,3940 ; U1_PZ3_b.7@7581,5170.51 7581,5114 7600,5095 7706.12,5095 C3_PZ3_b.2@7721,5109.88 v1(7721,5056) v1@7720,5055 ; U1_PZ3_a.7@7581,6285.51 7581,6229 7600,6210 7706.12,6210 C3_PZ3_a.2@7721,6224.88 v1(7721,6171) v1@7720,6170 ; v1(7736,2586) 7777.07,2586 D2_PZ3_d.1@7780,2583.07 ; v1(7736,3711) 7777.07,3711 D2_PZ3_c.1@7780,3708.07 ; v1(7736,4826) 7777.07,4826 D2_PZ3_b.1@7780,4823.07 ; v1(7736,5941) 7777.07,5941 D2_PZ3_a.1@7780,5938.07
  Top Layer w30: v1(7203.11,450) R38.2@7294.88,450 ; v1(7203.11,517.5) 7268.23,517.5 ; v1(7203.11,585) L1.2@7268.23,585 v1(7268.23,676.77)
  Top Layer w75: R38.2@7268.23,450 L1.2@7268.23,585
  Bottom Layer w20: L5.2@130,3191.77 v1(130,3255) ; L6.2@320,3191.77 v1(320,3255) ; R35.2@830.12,5565 972.91,5565 C28_U_diff_in_B.1@974.53,5566.61 ; C28_U_diff_in_D.1@970,3319.88 v1@1081.5,3319.88 ; C28_U_diff_in_C.1@970,4439.88 v1@1081.5,4439.88 ; C28_U_diff_in_B.1@970,5564.88 v1@1081.5,5564.88 ; C28_U_diff_in_A.1@970,6544.88 v1@1081.5,6544.88 ; C26_24dB_d.2@2311.12,3318 2311.12,3267.88 2342.93,3236.07 ; C26_24dB_c.2@2311.12,4413 2311.12,4362.88 2342.93,4331.07 ; C26_24dB_b.2@2311.12,5548 2311.12,5497.88 2342.93,5466.07 ; C26_24dB_a.2@2311.12,6638 2311.12,6587.88 2342.93,6556.07 ; D7_24dB_d.1@2342.93,3208 2342.93,3242.93 2356.63,3256.63 2359.39,3256.63 2364.89,3262.13 v1(2367.87,3262.13) ; D7_24dB_c.1@2342.93,4303 2342.93,4337.93 2356.63,4351.63 2359.39,4351.63 2364.89,4357.13 v1(2367.87,4357.13) ; D7_24dB_b.1@2342.93,5438 2342.93,5472.93 2356.63,5486.63 2359.39,5486.63 2364.89,5492.13 v1(2367.87,5492.13) ; D7_24dB_a.1@2342.93,6528 2342.93,6562.93 2356.63,6576.63 2359.39,6576.63 2364.89,6582.13 v1(2367.87,6582.13) ; C26_12dB_d.2@3281.12,3318 3281.12,3267.88 3312.93,3236.07 ; C26_12dB_c.2@3281.12,4413 3281.12,4362.88 3312.93,4331.07 ; C26_12dB_b.2@3281.12,5548 3281.12,5497.88 3312.93,5466.07 ; C26_12dB_a.2@3281.12,6638 3281.12,6587.88 3312.93,6556.07 ; D7_12dB_d.1@3312.93,3208 3312.93,3242.93 3326.63,3256.63 3329.39,3256.63 3334.89,3262.13 v1(3337.87,3262.13) ; D7_12dB_c.1@3312.93,4303 3312.93,4337.93 3326.63,4351.63 3329.39,4351.63 3334.89,4357.13 v1(3337.87,4357.13) ; D7_12dB_b.1@3312.93,5438 3312.93,5472.93 3326.63,5486.63 3329.39,5486.63 3334.89,5492.13 v1(3337.87,5492.13) ; D7_12dB_a.1@3312.93,6528 3312.93,6562.93 3326.63,6576.63 3329.39,6576.63 3334.89,6582.13 v1(3337.87,6582.13) ; C26_6dB_d.2@4251.12,3318 4251.12,3267.88 4282.93,3236.07 ; C26_6dB_c.2@4251.12,4413 4251.12,4362.88 4282.93,4331.07 ; C26_6dB_b.2@4251.12,5548 4251.12,5497.88 4282.93,5466.07 ; C26_6dB_a.2@4256.12,6638 4256.12,6587.88 4287.93,6556.07 ; D7_6dB_d.1@4282.93,3208 4282.93,3242.93 4296.63,3256.63 4299.39,3256.63 4304.89,3262.13 v1(4307.87,3262.13) ; D7_6dB_c.1@4282.93,4303 4282.93,4337.93 4296.63,4351.63 4299.39,4351.63 4304.89,4357.13 v1(4307.87,4357.13) ; D7_6dB_b.1@4282.93,5438 4282.93,5472.93 4296.63,5486.63 4299.39,5486.63 4304.89,5492.13 v1(4307.87,5492.13) ; D7_6dB_a.1@4287.93,6528 4287.93,6562.93 4301.63,6576.63 4304.39,6576.63 4309.89,6582.13 v1(4312.87,6582.13) ; C26_3dB_d.2@5221.12,3318 5221.12,3267.88 5252.93,3236.07 ; C26_3dB_c.2@5221.12,4413 5221.12,4362.88 5252.93,4331.07 ; C26_3dB_b.2@5221.12,5548 5221.12,5497.88 5252.93,5466.07 ; C26_3dB_a.2@5226.12,6638 5226.12,6587.88 5257.93,6556.07 ; D7_3dB_d.1@5252.93,3208 5252.93,3242.93 5266.63,3256.63 5269.39,3256.63 5274.89,3262.13 v1(5277.87,3262.13) ; D7_3dB_c.1@5252.93,4303 5252.93,4337.93 5266.63,4351.63 5269.39,4351.63 5274.89,4357.13 v1(5277.87,4357.13) ; D7_3dB_b.1@5252.93,5438 5252.93,5472.93 5266.63,5486.63 5269.39,5486.63 5274.89,5492.13 v1(5277.87,5492.13) ; D7_3dB_a.1@5257.93,6528 5257.93,6562.93 5271.63,6576.63 5274.39,6576.63 5279.89,6582.13 v1(5282.87,6582.13) ; v1(5700,1070) 5700,1134.88 C14.2@5705.12,1140 ; v1(5720,1775) 5720.12,1775.12 C8.2@5720.12,1845 ; C30_U_diff_out_C.1@6190.12,1125 6190.12,1099.88 v1(6230,1060) ; C30_U_diff_out_A.1@6195.12,1840 6195.12,1814.88 v1(6235,1775) ; v1(6930,1775) 6935.12,1780.12 C11.2@6935.12,1850 ; v1(6944,1056) 6944,1118.88 C17.2@6950.12,1125 ; C30_U_diff_out_D.1@7430.12,1125 7430.12,1099.88 v1(7470,1060) ; C30_U_diff_out_B.1@7430.12,1840 7430.12,1814.88 v1(7470,1775) ; v1(8020,3255) 8021.77,3253.23 L8.2@8115,3253.23 ; v1(8235,3180) 8308.23,3253.23 L7.2@8310,3253.23
-15: C1_PZ1_a.2 C1_PZ1_b.2 C1_PZ1_c.2 C1_PZ1_d.2 C1_PZ2_a.2 C1_PZ2_b.2 C1_PZ2_c.2 C1_PZ2_d.2 C1_PZ3_a.2 C1_PZ3_b.2 C1_PZ3_c.2 C1_PZ3_d.2 C6.2 C9.2 C12.2 C15.2 C22.1 C23.2 C24_3dB_a.2 C24_3dB_b.2 C24_3dB_c.2 C24_3dB_d.2 C24_6dB_a.2 C24_6dB_b.2 C24_6dB_c.2 C24_6dB_d.2 C24_12dB_a.2 C24_12dB_b.2 C24_12dB_c.2 C24_12dB_d.2 C24_24dB_a.2 C24_24dB_b.2 C24_24dB_c.2 C24_24dB_d.2 C29_U_diff_in_A.1 C29_U_diff_in_B.1 C29_U_diff_in_C.1 C29_U_diff_in_D.1 C31_U_diff_out_A.1 C31_U_diff_out_B.1 C31_U_diff_out_C.1 C31_U_diff_out_D.1 C32_U_logic_A.2 C32_U_logic_B.2 C32_U_logic_C.2 C32_U_logic_D.2 C36_U_logic_A.2 C36_U_logic_B.2 C36_U_logic_C.2 C36_U_logic_D.2 D1_PZ1_a.2 D1_PZ1_b.2 D1_PZ1_c.2 D1_PZ1_d.2 D1_PZ2_a.2 D1_PZ2_b.2 D1_PZ2_c.2 D1_PZ2_d.2 D1_PZ3_a.2 D1_PZ3_b.2 D1_PZ3_c.2 D1_PZ3_d.2 D6_3dB_a.2 D6_3dB_b.2 D6_3dB_c.2 D6_3dB_d.2 D6_6dB_a.2 D6_6dB_b.2 D6_6dB_c.2 D6_6dB_d.2 D6_12dB_a.2 D6_12dB_b.2 D6_12dB_c.2 D6_12dB_d.2 D6_24dB_a.2 D6_24dB_b.2 D6_24dB_c.2 D6_24dB_d.2 L2.2 R8.2 R9.2 R36.1 R39.2 TP6.1 U1_PZ1_a.4 U1_PZ1_b.4 U1_PZ1_c.4 U1_PZ1_d.4 U1_PZ2_a.4 U1_PZ2_b.4 U1_PZ2_c.4 U1_PZ2_d.4 U1_PZ3_a.4 U1_PZ3_b.4 U1_PZ3_c.4 U1_PZ3_d.4 U3.4 U4.4 U5.4 U6.4 U9_3dB_a.4 U9_3dB_b.4 U9_3dB_c.4 U9_3dB_d.4 U9_6dB_a.4 U9_6dB_b.4 U9_6dB_c.4 U9_6dB_d.4 U9_12dB_a.4 U9_12dB_b.4 U9_12dB_c.4 U9_12dB_d.4 U9_24dB_a.4 U9_24dB_b.4 U9_24dB_c.4 U9_24dB_d.4 U10_U_diff_in_A.13 U10_U_diff_in_B.13 U10_U_diff_in_C.13 U10_U_diff_in_D.13 U11_U_diff_out_A.4 U11_U_diff_out_B.4 U11_U_diff_out_C.4 U11_U_diff_out_D.4 U14_U_logic_A.4 U14_U_logic_B.4 U14_U_logic_C.4 U14_U_logic_D.4 U15_U_logic_A.4 U15_U_logic_B.4 U15_U_logic_C.4 U15_U_logic_D.4 | length 9805.4
  Top Layer w20: R8.2@165,6495.12 165,6525 v1(205,6565) ; v1(260.12,3565.12) R9.2@260.12,3625 ; v1(1230,3320) 1233.5,3316.5 U10_U_diff_in_D.13@1332.8,3316.5 ; v1(1230,4440) 1233.5,4436.5 U10_U_diff_in_C.13@1332.8,4436.5 ; v1(1230,5565) 1233.5,5561.5 U10_U_diff_in_B.13@1332.8,5561.5 ; v1(1230,6545) 1233.5,6541.5 U10_U_diff_in_A.13@1332.8,6541.5 ; v1@2121,3023 v1(2122.51,3024.51) U9_24dB_d.4@2122.51,3079 ; v1@2121,4118 v1(2122.51,4119.51) U9_24dB_c.4@2122.51,4174 ; v1@2121,5253 v1(2122.51,5254.51) U9_24dB_b.4@2122.51,5309 ; v1@2121,6343 v1(2122.51,6344.51) U9_24dB_a.4@2122.51,6399 ; v1@3091,3023 v1(3092.51,3024.51) U9_12dB_d.4@3092.51,3079 ; v1@3091,4118 v1(3092.51,4119.51) U9_12dB_c.4@3092.51,4174 ; v1@3091,5253 v1(3092.51,5254.51) U9_12dB_b.4@3092.51,5309 ; v1@3091,6343 v1(3092.51,6344.51) U9_12dB_a.4@3092.51,6399 ; U14_U_logic_A.4@3560,6069.36 v1(3560,6135) ; U14_U_logic_D.4@3565,2747.36 v1(3565,2815) ; U14_U_logic_C.4@3565,3867.36 v1(3565,3935) ; U14_U_logic_B.4@3565,4997.36 v1(3565,5065) ; U15_U_logic_A.4@4050,6069.36 v1(4050,6140) ; U15_U_logic_D.4@4055,2747.36 v1(4055,2815) ; U15_U_logic_C.4@4055,3867.36 v1(4055,3935) ; U15_U_logic_B.4@4055,4997.36 v1(4055,5065) ; v1@4061,3023 v1(4062.51,3024.51) U9_6dB_d.4@4062.51,3079 ; v1@4061,4118 v1(4062.51,4119.51) U9_6dB_c.4@4062.51,4174 ; v1@4061,5253 v1(4062.51,5254.51) U9_6dB_b.4@4062.51,5309 ; v1@4066,6343 v1(4067.51,6344.51) U9_6dB_a.4@4067.51,6399 ; v1@5031,3023 v1(5032.51,3024.51) U9_3dB_d.4@5032.51,3079 ; v1@5031,4118 v1(5032.51,4119.51) U9_3dB_c.4@5032.51,4174 ; v1@5031,5253 v1(5032.51,5254.51) U9_3dB_b.4@5032.51,5309 ; v1@5036,6343 v1(5037.51,6344.51) U9_3dB_a.4@5037.51,6399 ; v1@5545.51,1329.49 U5.4@5600,1329.49 ; v1@5565,2035 v1(5565.51,2034.49) U3.4@5620,2034.49 ; D1_PZ1_d.2@5678.07,2550 v1(5725,2550) ; D1_PZ1_c.2@5678.07,3675 v1(5725,3675) ; D1_PZ1_b.2@5678.07,4790 5712.02,4790 5722.02,4800 v1(5725,4800) ; D1_PZ1_a.2@5678.07,5905 v1(5725,5905) ; v1(5700,3240) 5700,3211.12 C1_PZ1_d.2@5731,3180.12 5791.63,3119.49 U1_PZ1_d.4@5811,3119.49 ; v1(5700,4365) 5700,4336.12 C1_PZ1_c.2@5731,4305.12 5791.63,4244.49 U1_PZ1_c.4@5811,4244.49 ; v1(5700,5480) 5700,5451.12 C1_PZ1_b.2@5731,5420.12 5791.63,5359.49 U1_PZ1_b.4@5811,5359.49 ; v1(5700,6595) 5700,6566.12 C1_PZ1_a.2@5731,6535.12 5791.63,6474.49 U1_PZ1_a.4@5811,6474.49 ; U11_U_diff_out_C.4@6040,1314.49 v1(6040,1385) ; U11_U_diff_out_A.4@6045,2029.49 v1(6045,2100) ; v1(6340,65) TP6.1@6340,155 ; v1(6500,155) C23.2@6615,155 ; D1_PZ2_d.2@6513.07,2550 v1(6560,2550) ; D1_PZ2_c.2@6513.07,3675 v1(6560,3675) ; D1_PZ2_b.2@6513.07,4790 v1(6560,4790) ; D1_PZ2_a.2@6513.07,5905 v1(6560,5905) ; v1(6535,3240) 6535,3211.12 C1_PZ2_d.2@6566,3180.12 6626.63,3119.49 U1_PZ2_d.4@6646,3119.49 ; v1(6535,4365) 6535,4336.12 C1_PZ2_c.2@6566,4305.12 6626.63,4244.49 U1_PZ2_c.4@6646,4244.49 ; v1(6535,5480) 6535,5451.12 C1_PZ2_b.2@6566,5420.12 6626.63,5359.49 U1_PZ2_b.4@6646,5359.49 ; v1(6535,6595) 6535,6566.12 C1_PZ2_a.2@6566,6535.12 6626.63,6474.49 U1_PZ2_a.4@6646,6474.49 ; v1(6765,105) C22.1@6765,159.88 ; v1@6775,2040 v1(6775.51,2039.49) U4.4@6830,2039.49 ; v1@6790,1315 v1(6790.49,1315.49) U6.4@6844,1315.49 ; U11_U_diff_out_D.4@7280,1314.49 v1(7280,1385) ; U11_U_diff_out_B.4@7280,2029.49 v1(7280,2100) ; D1_PZ3_d.2@7348.07,2550 v1(7395,2550) ; D1_PZ3_c.2@7348.07,3675 v1(7395,3675) ; D1_PZ3_b.2@7348.07,4790 v1(7395,4790) ; D1_PZ3_a.2@7348.07,5905 v1(7395,5905) ; v1(7370,3240) 7370,3211.12 C1_PZ3_d.2@7401,3180.12 7461.63,3119.49 U1_PZ3_d.4@7481,3119.49 ; v1(7370,4365) 7370,4336.12 C1_PZ3_c.2@7401,4305.12 7461.63,4244.49 U1_PZ3_c.4@7481,4244.49 ; v1(7370,5480) 7370,5451.12 C1_PZ3_b.2@7401,5420.12 7461.63,5359.49 U1_PZ3_b.4@7481,5359.49 ; v1(7370,6595) 7370,6566.12 C1_PZ3_a.2@7401,6535.12 7461.63,6474.49 U1_PZ3_a.4@7481,6474.49
  Top Layer w30: v1@260,3565 v1(260.12,3565.12) ; v1(7203.11,257.5) 7268.23,257.5 ; v1(7203.11,325) R39.2@7294.88,325 ; v1(7208.11,190) 7273.23,190 v1(7273.23,101.77)
  Top Layer w75: L2.2@7268.23,190 R39.2@7268.23,325
  Bottom Layer w20: v1(805,5910) 805.12,5910.12 R36.1@805.12,5980 ; v1(1230,3320) 1230.12,3319.88 C29_U_diff_in_D.1@1330,3319.88 ; v1(1230,4440) 1230.12,4439.88 C29_U_diff_in_C.1@1330,4439.88 ; v1(1230,5565) 1230.12,5564.88 C29_U_diff_in_B.1@1330,5564.88 ; v1(1230,6545) 1230.12,6544.88 C29_U_diff_in_A.1@1330,6544.88 ; v1(2122.51,3024.51) 2121,3026.02 C24_24dB_d.2@2121,3077.88 2125.88,3073 D6_24dB_d.2@2209.07,3073 ; v1(2122.51,4119.51) 2121,4121.02 C24_24dB_c.2@2121,4172.88 2125.88,4168 D6_24dB_c.2@2209.07,4168 ; v1(2122.51,5254.51) 2121,5256.02 C24_24dB_b.2@2121,5307.88 2125.88,5303 D6_24dB_b.2@2209.07,5303 ; v1(2122.51,6344.51) 2121,6346.02 C24_24dB_a.2@2121,6397.88 2125.88,6393 D6_24dB_a.2@2209.07,6393 ; v1(3092.51,3024.51) 3091,3026.02 C24_12dB_d.2@3091,3077.88 3095.88,3073 D6_12dB_d.2@3179.07,3073 ; v1(3092.51,4119.51) 3091,4121.02 C24_12dB_c.2@3091,4172.88 3095.88,4168 D6_12dB_c.2@3179.07,4168 ; v1(3092.51,5254.51) 3091,5256.02 C24_12dB_b.2@3091,5307.88 3095.88,5303 D6_12dB_b.2@3179.07,5303 ; v1(3092.51,6344.51) 3091,6346.02 C24_12dB_a.2@3091,6397.88 3095.88,6393 D6_12dB_a.2@3179.07,6393 ; v1(3560,6135) 3560,6075.12 C32_U_logic_A.2@3565.12,6070 ; v1(3565,2815) v1@3565.12,2814.88 ; v1(3565,5065) 3570.12,5059.88 C32_U_logic_B.2@3570.12,4997.36 ; C32_U_logic_D.2@3565.12,2725 v1@3565.12,2814.88 ; C32_U_logic_C.2@3565.12,3865 v1@3565.12,3934.88 ; v1@3570.12,2809.88 v1@3565.12,2814.88 ; v1(4050,6140) 4050.12,6139.88 C36_U_logic_A.2@4050.12,6070 ; v1(4055,2815) 4060.12,2809.88 C36_U_logic_D.2@4060.12,2745 ; v1(4055,3935) 4060.12,3929.88 C36_U_logic_C.2@4060.12,3865 ; v1(4055,5065) 4060.12,5059.88 C36_U_logic_B.2@4060.12,4997.36 ; v1(4062.51,3024.51) 4061,3026.02 C24_6dB_d.2@4061,3077.88 4065.88,3073 D6_6dB_d.2@4149.07,3073 ; v1(4062.51,4119.51) 4061,4121.02 C24_6dB_c.2@4061,4172.88 4065.88,4168 D6_6dB_c.2@4149.07,4168 ; v1(4062.51,5254.51) 4061,5256.02 C24_6dB_b.2@4061,5307.88 4065.88,5303 D6_6dB_b.2@4149.07,5303 ; v1(4067.51,6344.51) 4066,6346.02 C24_6dB_a.2@4066,6397.88 4070.88,6393 D6_6dB_a.2@4154.07,6393 ; v1(5032.51,3024.51) 5031,3026.02 C24_3dB_d.2@5031,3077.88 5035.88,3073 D6_3dB_d.2@5119.07,3073 ; v1(5032.51,4119.51) 5031,4121.02 C24_3dB_c.2@5031,4172.88 5035.88,4168 D6_3dB_c.2@5119.07,4168 ; v1(5032.51,5254.51) 5031,5256.02 C24_3dB_b.2@5031,5307.88 5035.88,5303 D6_3dB_b.2@5119.07,5303 ; v1(5037.51,6344.51) 5036,6346.02 C24_3dB_a.2@5036,6397.88 5040.88,6393 D6_3dB_a.2@5124.07,6393 ; v1(5545,1330) 5550,1335 C12.2@5599.88,1335 ; v1(5565.51,2034.49) 5566.02,2035 C6.2@5624.88,2035 ; C31_U_diff_out_C.1@6039.88,1315 6039.88,1384.88 v1(6040,1385) ; C31_U_diff_out_A.1@6044.88,2030 6044.88,2099.88 v1(6045,2100) ; v1(6775.51,2039.49) 6780,2035 C9.2@6839.88,2035 ; v1(6790.49,1315.49) 6790.98,1315 C15.2@6849.88,1315 ; C31_U_diff_out_D.1@7279.88,1315 7279.88,1384.88 v1(7280,1385) ; C31_U_diff_out_B.1@7279.88,2030 7279.88,2099.88 v1(7280,2100)
A1: U8_24dB_a.1 U8_24dB_a.9 U13_U_logic_A.19 U14_U_logic_A.1 | length 1914.8
  Top Layer w12: U8_24dB_a.9@2443.78,6667.36 2443.95,6667.53 2477.87,6667.53 2487.34,6677 2572.86,6677 2584.86,6665 v1(2590,6665) ; v1(2605,6488.23) U8_24dB_a.1@2666.22,6488.23
  Top Layer w15: v1(2605,6488.23) 2715,6378.23 2715,6307 2795,6227 ; U13_U_logic_A.19@2795,6153.1 2795,6227 ; U14_U_logic_A.1@3710,6069.36 3710,6227 3685,6252 2820,6252 2795,6227
  MidLayer1 w12: v1(2590,6665) 2615,6640 2615,6503.37 2605,6493.37 v1(2605,6488.23)
A2: U8_12dB_a.1 U8_12dB_a.9 U13_U_logic_A.18 U14_U_logic_A.16 | length 2793.6
  Top Layer w12: U8_12dB_a.9@3413.78,6667.36 3413.95,6667.53 3447.87,6667.53 3457.34,6677 3542.86,6677 3554.86,6665 v1(3560,6665) ; v1(3575,6488.23) U8_12dB_a.1@3636.22,6488.23
  Top Layer w15: U13_U_logic_A.18@2845,6153.1 v1(2845,6030) 2845,5972 2915,5902 3205,5902 3250,5857 3250,5772 3280,5742 3695,5742 3710,5757 U14_U_logic_A.16@3710,5864.64
  MidLayer1 w12: v1(3560,6665) 3585,6640 3585,6503.37 3575,6493.37 v1(3575,6488.23)
  MidLayer1 w15: v1(2845,6030) 2845,6305 2970,6430 3516.77,6430 v1(3575,6488.23)
A3: U8_6dB_a.1 U8_6dB_a.9 U13_U_logic_A.17 U14_U_logic_A.9 | length 3090.2
  Top Layer w12: U8_6dB_a.9@4388.78,6667.36 4388.95,6667.53 4422.87,6667.53 4432.34,6677 4517.86,6677 4529.86,6665 v1(4535,6665) ; v1(4550,6488.23) U8_6dB_a.1@4611.22,6488.23
  Top Layer w15: U13_U_logic_A.17@2895,6153.1 v1(2895,6060) 2895,5972 2930,5937 3215,5937 3287.36,5864.64 U14_U_logic_A.9@3360,5864.64
  MidLayer1 w12: v1(4535,6665) 4560,6640 4560,6503.37 4550,6493.37 v1(4550,6488.23)
  MidLayer1 w15: v1(2895,6060) 2895,6290 2985,6380 3215,6380 3245,6350 3575,6350 3655,6430 4491.77,6430 v1(4550,6488.23)
A4: U8_3dB_a.1 U8_3dB_a.9 U13_U_logic_A.16 U14_U_logic_A.8 | length 4062.2
  Top Layer w12: U8_3dB_a.9@5358.78,6667.36 5358.95,6667.53 5392.87,6667.53 5402.34,6677 5487.86,6677 5499.86,6665 v1(5505,6665) ; v1(5520,6488.23) U8_3dB_a.1@5581.22,6488.23
  Top Layer w15: v1(2945,6030) U13_U_logic_A.16@2945,6153.1 2945,6217 2955,6227 3345,6227 3360,6212 U14_U_logic_A.8@3360,6069.36
  MidLayer1 w12: v1(5505,6665) 5530,6640 5530,6503.37 5520,6493.37 v1(5520,6488.23)
  MidLayer1 w15: v1(2945,6030) 2945,6260 2990,6305 5336.77,6305 5461.77,6430 v1(5520,6488.23)
A5: U2_PZ1_a.1 U2_PZ1_a.9 U13_U_logic_A.15 U15_U_logic_A.1 | length 5085.7
  Top Layer w12: v1(5700,6125) 5700.43,6124.57 U2_PZ1_a.1@5773.78,6124.57 ; v1(5900,5925) 5920.43,5945.43 U2_PZ1_a.9@5996.22,5945.43
  Top Layer w15: v1(2995,6062) U13_U_logic_A.15@2995,6153.1 ; U15_U_logic_A.1@4200,6069.36 v1(4200,6142)
  MidLayer1 w15: v1(2995,6062) 2995,6235 3030,6270 5555,6270 v1(5700,6125) 5780,6045 5845,6045 5870,6020 5870,5955 v1(5900,5925)
  Bottom Layer w15: v1(2995,6062) 2995,6217 3030,6252 4175,6252 4200,6227 v1(4200,6142)
A6: U2_PZ2_a.1 U2_PZ2_a.9 U13_U_logic_A.14 U15_U_logic_A.16 | length 6504.2
  Top Layer w12: v1(6535,6125) 6535.43,6124.57 U2_PZ2_a.1@6608.78,6124.57 ; v1(6735,5925) 6755.43,5945.43 U2_PZ2_a.9@6831.22,5945.43
  Top Layer w15: v1(3045,6032) U13_U_logic_A.14@3045,6153.1 ; U15_U_logic_A.16@4200,5864.64 4222.64,5864.64 4245,5887 v1(4245,6102)
  MidLayer1 w15: v1(3045,6032) 3045,6180 3085,6220 5545,6220 5635,6130 5635,5940 5760,5815 6625,5815 v1(6735,5925) 6705,5955 6705,6020 6680,6045 6615,6045 v1(6535,6125)
  Bottom Layer w15: v1(3045,6032) 3045,6207 3065,6227 4050,6227 4175,6102 v1(4245,6102)
A7: U2_PZ3_a.1 U2_PZ3_a.9 U13_U_logic_A.13 U15_U_logic_A.9 | length 6635.9
  Top Layer w12: v1(7370,6125) 7370.43,6124.57 U2_PZ3_a.1@7443.78,6124.57 ; v1(7570,5925) 7590.43,5945.43 U2_PZ3_a.9@7666.22,5945.43
  Top Layer w15: v1(3095,6062) U13_U_logic_A.13@3095,6153.1 ; v1(3805,6112) 3805,6007 3850,5962 U15_U_logic_A.9@3850,5864.64
  MidLayer1 w15: v1(3095,6062) 3095,6145 3130,6180 5535,6180 5590,6125 5590,5935 5750,5775 7420,5775 v1(7570,5925) 7540,5955 7540,6020 7515,6045 7450,6045 v1(7370,6125)
  Bottom Layer w15: v1(3095,6062) 3095,6172 3120,6197 3720,6197 v1(3805,6112)
AN_1: IN1.2 J5.9 R22_U_diff_in_A.1 R33_U_diff_in_A.2 | length 3704.2
  Top Layer w15: v1(520,6755) 445,6680 125,6680 90,6645 90,5225 172.17,5142.83 J5.9@318.11,5142.83 318.11,5076.89 545,4850 IN1.2@800,4850 ; v1(695,6685) R33_U_diff_in_A.2@754.88,6685
  Bottom Layer w15: v1(520,6755) R22_U_diff_in_A.1@694.88,6755 ; v1(695,6685) R22_U_diff_in_A.1@695,6754.88 ; IN1.2@800,4850 IN1.2@1000,4850 IN1.2@1000,5050 IN1.2@800,5050
AN_2: IN2.2 J5.10 R22_U_diff_in_B.1 R33_U_diff_in_B.2 | length 2766
  Top Layer w15: v1(695,5705) R33_U_diff_in_B.2@754.88,5705
  Bottom Layer w15: J5.10@318.11,5251.89 268.11,5251.89 240,5280 240,5600 275,5635 350,5635 405,5690 575,5690 590,5705 v1(695,5705) ; R22_U_diff_in_B.1@695,5774.88 v1(695,5705) ; IN2.2@1250,4850 IN2.2@1450,4850 IN2.2@1450,5050 IN2.2@1250,5050 1160,5140 1160,5655 1110,5705 v1(695,5705)
AN_3: IN3.2 J5.11 R22_U_diff_in_C.1 R33_U_diff_in_C.2 | length 2687.5
  Top Layer w15: v1(695,4585) 749.88,4585 R33_U_diff_in_C.2@754.88,4580
  MidLayer1 w15: J5.11@318.11,5360.94 379.15,5299.9 379.15,5175.49 409.64,5145 495,5145 560,5080 560,4605 580,4585 v1(695,4585)
  Bottom Layer w15: R22_U_diff_in_C.1@695,4649.88 v1(695,4585) 625,4585 575,4535 575,4035 685,3925 IN3.2@800,3925 IN3.2@1000,3925 IN3.2@1000,3725 IN3.2@800,3725
AN_4: IN4.2 J5.12 R22_U_diff_in_D.1 R33_U_diff_in_D.2 | length 3795.9
  Top Layer w15: v1(695,3460) R33_U_diff_in_D.2@754.88,3460
  Bottom Layer w15: J5.12@318.11,5470 475,5470 545,5400 545,3700 545,3480 565,3460 v1(695,3460) R22_U_diff_in_D.1@695,3529.88 ; 545,3660 1185,3660 IN4.2@1250,3725 IN4.2@1450,3725 IN4.2@1450,3925 IN4.2@1250,3925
